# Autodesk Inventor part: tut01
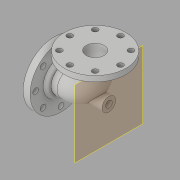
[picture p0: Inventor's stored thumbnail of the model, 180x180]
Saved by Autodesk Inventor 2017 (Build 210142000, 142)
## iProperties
Created: 2015-03
Part Number: tut01
Material: Generic
Document SubType Name: Modeling
Designer: Sandeep
Density: 1 g/cm^3
Appearance: Default
Author: Sandeep
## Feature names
1. Sweep1
2. Shell1
3. Extrusion1
4. Extrusion2
5. Extrusion3
6. Extrusion4
7. Fillet1
8. Extrusion5
9. Circular Pattern1
10. Extrusion6
11. Circular Pattern2
12. Extrusion7
13. Hole1
## Parameters: d1 = 35 mm, d2 = 35 mm, d4 = 97 mm, d5 = 0, d6 = 0, d7 = 16 mm, d8 = 225 mm, d10 = 0, d11 = 225 mm, d13 = 25 mm, d14 = 0, d15 = 86 mm, d16 = 22 mm, d17 = 0, d18 = 129 mm, d19 = 16 mm, d20 = 0, d21 = 16 mm, d22 = 185 mm, d23 = 20.5 mm, d24 = 0, d25 = 0, d27 = 360 deg, d29 = 185 mm, d30 = 20.5 mm, d31 = 16 mm, d32 = 0, d34 = 360 deg, d37 = 175 mm, d39 = 145 mm, d40 = 16 mm, d41 = 0, d45 = 6 mm, d46 = 24 mm, d47 = 28 mm, d48 = 90 deg, d49 = 8 mm, d50 = 118 deg
